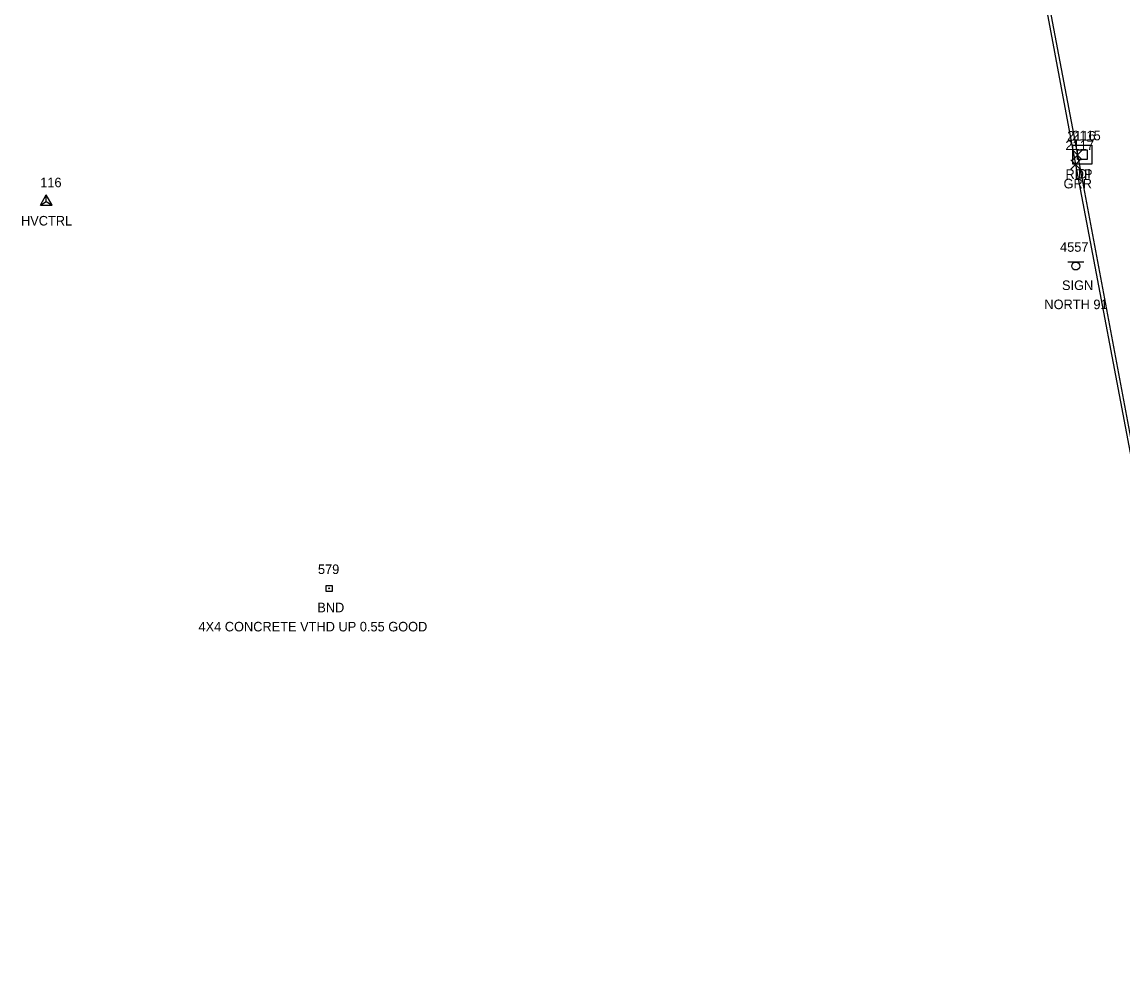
# Model space of a CAD drawing. Extents: x 1690689 to 1696275, y 438760 to 444007.
# Drawn here: x 1691206.6 to 1691436.8, y 439854.7 to 440051.3 of the extents above; entities that cross this region are included whole.
import ezdxf

# ---------------------------------------------------------------- set-up
doc = ezdxf.new("R2010")
doc.units = 0
for name, color, linetype in [('C_A', 7, 'Continuous'), ('C_I', 7, 'Continuous'), ('CPSM', 7, 'Continuous'), ('D_A', 7, 'Continuous'), ('D_I', 7, 'Continuous'), ('DS', 7, 'Continuous'), ('Level 18', 7, 'Continuous'), ('M_A', 7, 'Continuous'), ('M_C', 7, 'Continuous'), ('M_I', 7, 'Continuous'), ('P_A', 7, 'Continuous'), ('P_I', 7, 'Continuous'), ('P_TIC', 7, 'Continuous'), ('PET', 7, 'Continuous'), ('R_A', 7, 'Continuous'), ('R_I', 7, 'Continuous'), ('R_TIC', 7, 'Continuous'), ('RGR', 7, 'Continuous'), ('S_A', 7, 'Continuous'), ('S_C', 7, 'Continuous'), ('S_I', 7, 'Continuous'), ('SSGN', 7, 'Continuous')]:
    doc.layers.add(name, color=color, linetype=linetype)

msp = doc.modelspace()

# ---------------------------------------------------------------- linework, layer by layer
at = {"layer": 'CPSM'}
for p, q in [((1691210.41, 440013.01), (1691211.66, 440015.18)), ((1691210.41, 440013.01), (1691211.66, 440013.74)), ((1691212.91, 440013.01), (1691211.66, 440015.18)), ((1691211.66, 440013.74), (1691211.66, 440015.18)), ((1691211.66, 440013.74), (1691211.66, 440013.74)), ((1691211.66, 440013.74), (1691212.91, 440013.01)), ((1691210.41, 440013.01), (1691212.91, 440013.01))]:
    msp.add_line(p, q, dxfattribs=at)
at = {"layer": 'DS'}
for p, q in [((1691426.33, 440025.55), (1691430.33, 440025.55)), ((1691426.33, 440021.55), (1691426.33, 440025.55)), ((1691427.33, 440022.55), (1691427.33, 440024.55)), ((1691427.33, 440024.55), (1691429.33, 440024.55)), ((1691429.33, 440024.55), (1691429.33, 440022.55)), ((1691430.33, 440025.55), (1691430.33, 440021.55)), ((1691429.33, 440022.55), (1691427.33, 440022.55)), ((1691428.34, 440023.55), (1691428.34, 440023.55)), ((1691428.34, 440023.55), (1691428.34, 440023.55)), ((1691430.33, 440021.55), (1691426.33, 440021.55))]:
    msp.add_line(p, q, dxfattribs=at)
at = {"layer": 'Level 18'}
msp.add_lwpolyline([(1691270.2, 439933.48), (1691271.45, 439933.48), (1691271.45, 439932.23), (1691270.2, 439932.23)], close=True, dxfattribs=at)
msp.add_circle((1691270.83, 439932.86), 0.0833, dxfattribs=at)
at = {"layer": 'P_TIC'}
for points in [[(1691426.31, 440022.49), (1691428.31, 440024.49)], [(1691428.31, 440022.49), (1691426.31, 440024.49)]]:
    msp.add_lwpolyline(points, dxfattribs=at)
at = {"layer": 'PET'}
msp.add_lwpolyline([(1691377.54, 440285.07), (1691383.03, 440263.99), (1691389.71, 440226.83), (1691397.52, 440183.99), (1691405.42, 440141.12), (1691420.18, 440061.02), (1691427.31, 440023.49), (1691441.11, 439949.89), (1691451.37, 439894.72), (1691461.75, 439846.42), (1691469.53, 439815.36), (1691477.9, 439786.08), (1691489.83, 439749.54), (1691508.6, 439697.41), (1691528.81, 439647.65), (1691555.7, 439590.13)], dxfattribs=at)
at = {"layer": 'R_TIC'}
for points in [[(1691425.89, 440020.5), (1691427.89, 440022.5)], [(1691427.89, 440020.5), (1691425.89, 440022.5)]]:
    msp.add_lwpolyline(points, dxfattribs=at)
at = {"layer": 'RGR'}
msp.add_lwpolyline([(1691377.05, 440284.73), (1691382.32, 440263.95), (1691388.93, 440226.77), (1691396.89, 440183.97), (1691404.66, 440141.15), (1691419.49, 440061.06), (1691426.89, 440021.5), (1691440.31, 439950.53), (1691450.78, 439894.67), (1691460.99, 439846.23), (1691468.83, 439815.05), (1691476.97, 439785.63), (1691488.62, 439749.74), (1691507.91, 439696.82), (1691528.09, 439647.02), (1691554.98, 439589.81)], dxfattribs=at)
at = {"layer": 'SSGN'}
for p, q in [((1691425.28, 440001.11), (1691428.61, 440001.11)), ((1691426.93, 440000.27), (1691426.93, 440000.27))]:
    msp.add_line(p, q, dxfattribs=at)
msp.add_circle((1691426.93, 440000.27), 0.833, dxfattribs=at)

# ---------------------------------------------------------------- texts
at = {"layer": 'C_A'}
msp.add_text('HVCTRL', height=2, dxfattribs=at).set_placement((1691206.36, 440008.74))
at = {"layer": 'C_I'}
msp.add_text('116', height=2, dxfattribs=at).set_placement((1691210.38, 440016.74))
at = {"layer": 'D_A'}
msp.add_text('DI', height=2, dxfattribs=at).set_placement((1691427.39, 440018.55))
at = {"layer": 'D_I'}
msp.add_text('2115', height=2, dxfattribs=at).set_placement((1691426.21, 440026.55))
at = {"layer": 'M_A'}
msp.add_text('BND', height=2, dxfattribs=at).set_placement((1691268.32, 439927.86))
at = {"layer": 'M_C'}
msp.add_text('4X4 CONCRETE VTHD UP 0.55 GOOD', height=2, dxfattribs=at).set_placement((1691243.48, 439923.86))
at = {"layer": 'M_I'}
msp.add_text('579', height=2, dxfattribs=at).set_placement((1691268.46, 439935.86))
at = {"layer": 'P_A'}
msp.add_text('RDP', height=2, dxfattribs=at).set_placement((1691424.79, 440018.49))
at = {"layer": 'P_I'}
msp.add_text('2116', height=2, dxfattribs=at).set_placement((1691425.13, 440026.49))
at = {"layer": 'R_A'}
msp.add_text('GRR', height=2, dxfattribs=at).set_placement((1691424.38, 440016.5))
at = {"layer": 'R_I'}
msp.add_text('2117', height=2, dxfattribs=at).set_placement((1691424.77, 440024.5))
at = {"layer": 'S_A'}
msp.add_text('SIGN', height=2, dxfattribs=at).set_placement((1691424.06, 439995.25))
at = {"layer": 'S_C'}
msp.add_text('NORTH 91', height=2, dxfattribs=at).set_placement((1691420.37, 439991.25))
at = {"layer": 'S_I'}
msp.add_text('4557', height=2, dxfattribs=at).set_placement((1691423.65, 440003.25))

doc.saveas('drawing.dxf')
